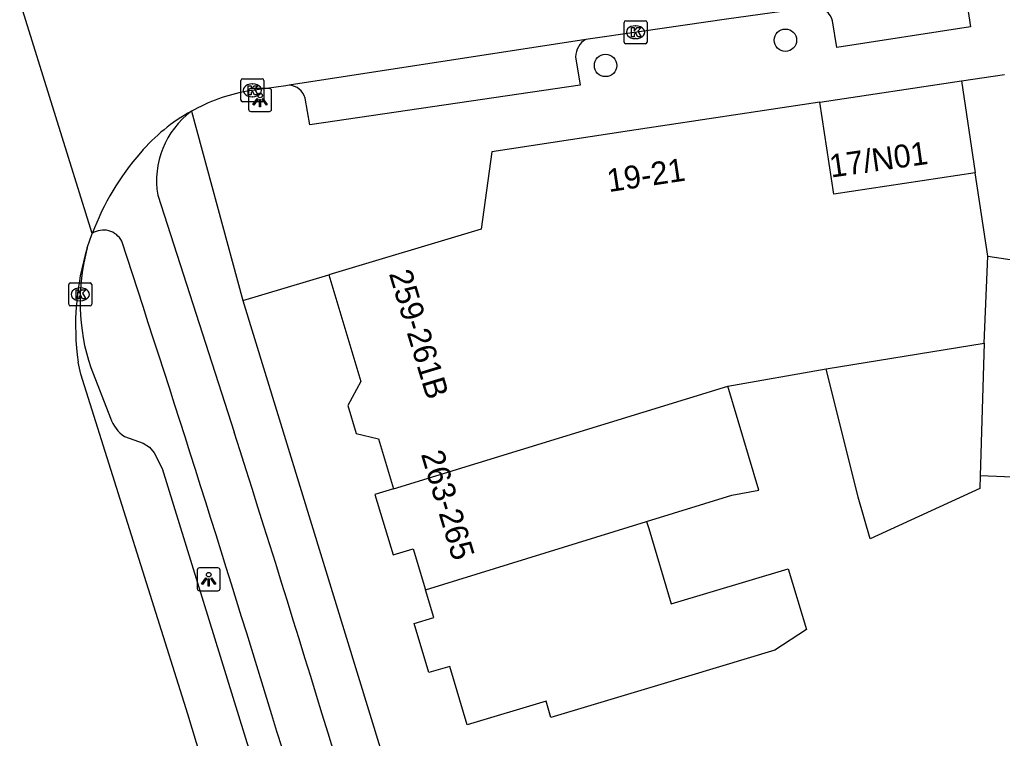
# Model space of a CAD drawing. Extents: x 162347 to 162868, y 381221 to 381813.
# Drawn here: x 162506 to 162548.83, y 381328.51 to 381359.83 of the extents above; entities that cross this region are included whole.
import ezdxf

# ---------------------------------------------------------------- set-up
doc = ezdxf.new("R2010")
doc.units = 0
for name, color, linetype in [('IMGEO_Boom', 7, 'Continuous'), ('IMGEO_Fietspad_open', 7, 'Continuous'), ('IMGEO_Kolk', 7, 'Continuous'), ('IMGEO_Lichtpunt', 7, 'Continuous'), ('IMGEO_Pand', 7, 'Continuous'), ('IMGEO_Pand_nummerreeks', 7, 'Continuous'), ('IMGEO_Parkeervlak_open', 7, 'Continuous'), ('IMGEO_Rijbaan_lokaal_gesloten', 7, 'Continuous'), ('IMGEO_Rijbaan_regionaal_gesloten', 7, 'Continuous'), ('IMGEO_Voetpad_open', 7, 'Continuous')]:
    doc.layers.add(name, color=color, linetype=linetype)

msp = doc.modelspace()

# ---------------------------------------------------------------- linework, layer by layer
at = {"layer": 'IMGEO_Boom'}
for centre in [(162539.372, 381358.93), (162531.535, 381357.832)]:
    msp.add_circle(centre, 0.489, dxfattribs=at)
at = {"layer": 'IMGEO_Fietspad_open'}
msp.add_lwpolyline([(162512.017, 381352.181), (162515.348, 381341.849)], dxfattribs=at)
for centre, radius, start, end in [((162515.746, 381352.807), 3.781, 126.7231, 189.5336), ((162509.653, 381349.759), 0.898, 27.2906, 122.9242), ((161424.172, 380994.375), 1143.063, 16.937549, 18.135487), ((161515.414, 381022.471), 1049.7, 16.214141, 17.713421)]:
    msp.add_arc(centre, radius, start, end, dxfattribs=at)
at = {"layer": 'IMGEO_Kolk'}
for p, q in [((162532.344, 381358.853), (162532.344, 381359.705)), ((162532.419, 381359.779), (162533.271, 381359.779)), ((162533.345, 381359.705), (162533.345, 381358.853)), ((162532.832, 381359.559), (162532.857, 381359.559)), ((162533.271, 381358.779), (162532.419, 381358.779)), ((162532.855, 381358.999), (162532.83, 381358.999)), ((162515.643, 381356.323), (162515.643, 381357.175)), ((162515.718, 381357.249), (162516.57, 381357.249)), ((162516.644, 381357.175), (162516.644, 381356.323)), ((162516.131, 381357.029), (162516.156, 381357.029)), ((162516.57, 381356.249), (162515.718, 381356.249)), ((162516.154, 381356.469), (162516.129, 381356.469)), ((162508.143, 381347.429), (162508.143, 381348.281)), ((162508.218, 381348.355), (162509.07, 381348.355)), ((162508.631, 381348.135), (162508.656, 381348.135)), ((162509.144, 381348.281), (162509.144, 381347.429)), ((162509.07, 381347.355), (162508.218, 381347.355)), ((162508.654, 381347.575), (162508.629, 381347.575))]:
    msp.add_line(p, q, dxfattribs=at)
for points in [[(162532.344, 381358.853), (162532.344, 381359.705)], [(162532.419, 381359.779), (162533.271, 381359.779)], [(162533.345, 381359.705), (162533.345, 381358.853)], [(162532.665, 381359.479), (162532.788, 381359.479), (162532.788, 381359.328), (162532.918, 381359.479), (162533.082, 381359.479), (162532.936, 381359.328), (162533.089, 381359.079), (162532.937, 381359.079), (162532.852, 381359.243), (162532.788, 381359.176), (162532.788, 381359.079), (162532.665, 381359.079), (162532.665, 381359.479)], [(162533.271, 381358.779), (162532.419, 381358.779)], [(162515.643, 381356.323), (162515.643, 381357.175)], [(162515.718, 381357.249), (162516.57, 381357.249)], [(162516.644, 381357.175), (162516.644, 381356.323)], [(162515.964, 381356.949), (162516.087, 381356.949), (162516.087, 381356.798), (162516.217, 381356.949), (162516.381, 381356.949), (162516.235, 381356.798), (162516.388, 381356.549), (162516.236, 381356.549), (162516.151, 381356.713), (162516.087, 381356.646), (162516.087, 381356.549), (162515.964, 381356.549), (162515.964, 381356.949)], [(162516.57, 381356.249), (162515.718, 381356.249)], [(162508.143, 381347.429), (162508.143, 381348.281)], [(162508.218, 381348.355), (162509.07, 381348.355)], [(162509.144, 381348.281), (162509.144, 381347.429)], [(162508.464, 381348.055), (162508.587, 381348.055), (162508.587, 381347.904), (162508.717, 381348.055), (162508.881, 381348.055), (162508.735, 381347.904), (162508.888, 381347.655), (162508.736, 381347.655), (162508.651, 381347.819), (162508.587, 381347.752), (162508.587, 381347.655), (162508.464, 381347.655), (162508.464, 381348.055)], [(162509.07, 381347.355), (162508.218, 381347.355)]]:
    msp.add_lwpolyline(points, dxfattribs=at)
for centre, start, end in [((162532.421, 381359.703), 91.552, 178.448), ((162532.421, 381359.703), 91.552, 178.448), ((162533.269, 381359.703), 1.552, 88.448), ((162533.269, 381359.703), 1.552, 88.448), ((162532.421, 381358.855), 181.552, 268.448), ((162532.421, 381358.855), 181.552, 268.448), ((162533.269, 381358.855), 271.552, 358.448), ((162533.269, 381358.855), 271.552, 358.448), ((162515.72, 381357.173), 91.552, 178.448), ((162515.72, 381357.173), 91.552, 178.448), ((162516.568, 381357.173), 1.552, 88.448), ((162516.568, 381357.173), 1.552, 88.448), ((162515.72, 381356.325), 181.552, 268.448), ((162515.72, 381356.325), 181.552, 268.448), ((162516.568, 381356.325), 271.552, 358.448), ((162516.568, 381356.325), 271.552, 358.448), ((162508.22, 381348.279), 91.552, 178.448), ((162508.22, 381348.279), 91.552, 178.448), ((162509.068, 381348.279), 1.552, 88.448), ((162509.068, 381348.279), 1.552, 88.448), ((162508.22, 381347.431), 181.552, 268.448), ((162508.22, 381347.431), 181.552, 268.448), ((162509.068, 381347.431), 271.552, 358.448), ((162509.068, 381347.431), 271.552, 358.448)]:
    msp.add_arc(centre, 0.0765, start, end, dxfattribs=at)
for centre, major_axis, ratio, start_param, end_param in [((162532.831, 381359.279), (-0.387, 0.002), 0.722429, 4.712389, 7.853982), ((162532.856, 381359.279), (-0.39, 0.002), 0.717154, 1.570796, 4.712389), ((162516.13, 381356.749), (-0.387, 0.002), 0.722429, 4.712389, 7.853982), ((162516.155, 381356.749), (-0.39, 0.002), 0.717154, 1.570796, 4.712389), ((162508.63, 381347.855), (-0.387, 0.002), 0.722429, 4.712389, 7.853982), ((162508.655, 381347.855), (-0.39, 0.002), 0.717154, 1.570796, 4.712389)]:
    msp.add_ellipse(centre, major_axis=major_axis, ratio=ratio, start_param=start_param, end_param=end_param, dxfattribs=at)
at = {"layer": 'IMGEO_Lichtpunt'}
for p, q in [((162515.981, 381356.729), (162515.981, 381355.922)), ((162515.981, 381356.729), (162515.981, 381355.922)), ((162516.883, 381356.824), (162516.075, 381356.824)), ((162516.883, 381356.824), (162516.075, 381356.824)), ((162516.977, 381355.922), (162516.977, 381356.729)), ((162516.977, 381355.922), (162516.977, 381356.729)), ((162516.075, 381355.828), (162516.883, 381355.828)), ((162516.075, 381355.828), (162516.883, 381355.828)), ((162513.742, 381335.841), (162513.742, 381335.034)), ((162513.742, 381335.841), (162513.742, 381335.034)), ((162514.644, 381335.936), (162513.836, 381335.936)), ((162514.644, 381335.936), (162513.836, 381335.936)), ((162514.738, 381335.034), (162514.738, 381335.841)), ((162514.738, 381335.034), (162514.738, 381335.841)), ((162513.836, 381334.94), (162514.644, 381334.94)), ((162513.836, 381334.94), (162514.644, 381334.94))]:
    msp.add_line(p, q, dxfattribs=at)
for points in [[(162516.355, 381356.393), (162516.394, 381356.365), (162516.206, 381356.103), (162516.168, 381356.13), (162516.355, 381356.393)], [(162516.457, 381356.345), (162516.504, 381356.345), (162516.504, 381356.023), (162516.457, 381356.023), (162516.457, 381356.345)], [(162516.567, 381356.365), (162516.605, 381356.392), (162516.792, 381356.13), (162516.753, 381356.102), (162516.567, 381356.365)], [(162514.116, 381335.505), (162514.155, 381335.477), (162513.967, 381335.215), (162513.929, 381335.242), (162514.116, 381335.505)], [(162514.218, 381335.457), (162514.265, 381335.457), (162514.265, 381335.135), (162514.218, 381335.135), (162514.218, 381335.457)], [(162514.328, 381335.477), (162514.366, 381335.504), (162514.553, 381335.242), (162514.514, 381335.214), (162514.328, 381335.477)]]:
    msp.add_lwpolyline(points, dxfattribs=at)
for centre in [(162516.48, 381356.527), (162514.241, 381335.639)]:
    msp.add_circle(centre, 0.0994, dxfattribs=at)
for centre, start, end in [((162516.075, 381356.729), 90, 180), ((162516.075, 381356.729), 90, 180), ((162516.883, 381356.729), 0, 90), ((162516.883, 381356.729), 0, 90), ((162516.075, 381355.922), 180, 270), ((162516.075, 381355.922), 180, 270), ((162516.883, 381355.922), 270, 0), ((162516.883, 381355.922), 270, 360), ((162513.836, 381335.841), 90, 180), ((162513.836, 381335.841), 90, 180), ((162514.644, 381335.841), 0, 90), ((162514.644, 381335.841), 0, 90), ((162513.836, 381335.034), 180, 270), ((162513.836, 381335.034), 180, 270), ((162514.644, 381335.034), 270, 0), ((162514.644, 381335.034), 270, 360)]:
    msp.add_arc(centre, 0.0946, start, end, dxfattribs=at)
at = {"layer": 'IMGEO_Pand'}
for points in [[(162540.878, 381356.227), (162547.044, 381357.157)], [(162547.044, 381357.157), (162547.648, 381353.152)], [(162540.878, 381356.227), (162532.585, 381354.976), (162526.582, 381354.07), (162526.112, 381350.704), (162519.471, 381348.712)], [(162547.648, 381353.152), (162541.482, 381352.222), (162540.878, 381356.227)], [(162548.193, 381349.527), (162547.648, 381353.152)], [(162548.193, 381349.527), (162550.914, 381349.118), (162560.676, 381347.652), (162560.347, 381339.448), (162551.036, 381339.821), (162547.859, 381339.948)], [(162548.037, 381345.733), (162548.193, 381349.527)], [(162519.471, 381348.712), (162520.864, 381344.065), (162520.296, 381343.01), (162520.66, 381341.796), (162521.639, 381341.564), (162522.296, 381339.376)], [(162541.145, 381344.608), (162548.037, 381345.733)], [(162548.037, 381345.733), (162547.859, 381339.948)], [(162536.857, 381343.859), (162541.145, 381344.608)], [(162547.859, 381339.948), (162547.841, 381339.39), (162543.063, 381337.202), (162542.54, 381339.013), (162541.145, 381344.608)], [(162522.296, 381339.376), (162536.857, 381343.859)], [(162533.322, 381337.952), (162537.044, 381339.099), (162538.218, 381339.323), (162536.857, 381343.859)], [(162522.296, 381339.376), (162521.487, 381339.134), (162522.276, 381336.504), (162523.155, 381336.768), (162523.69, 381334.985)], [(162533.322, 381337.952), (162533.414, 381337.645), (162534.399, 381334.362), (162539.5, 381335.892), (162540.291, 381333.255), (162538.907, 381332.343), (162533.941, 381330.854), (162529.151, 381329.417), (162528.94, 381330.122), (162525.508, 381329.093), (162524.744, 381331.642), (162523.837, 381331.37), (162523.195, 381333.509), (162524.055, 381333.767), (162523.69, 381334.985)], [(162523.69, 381334.985), (162533.322, 381337.952)]]:
    msp.add_lwpolyline(points, dxfattribs=at)
at = {"layer": 'IMGEO_Parkeervlak_open'}
for points in [[(162509.097, 381344.675), (162509.963, 381342.467)], [(162510.574, 381341.66), (162511.386, 381341.368), (162511.659, 381341.199), (162511.867, 381340.946), (162512.219, 381340.273), (162517.818, 381322.123), (162520.103, 381314.39), (162520.562, 381312.814), (162522.874, 381305.299), (162525.989, 381295.243), (162527.307, 381291.065)]]:
    msp.add_lwpolyline(points, dxfattribs=at)
for centre, radius, start, end in [((162517.554, 381347.52), 8.922, 164.6666, 198.5914), ((162511.426, 381342.94), 1.537, 197.9086, 236.3519)]:
    msp.add_arc(centre, radius, start, end, dxfattribs=at)
at = {"layer": 'IMGEO_Rijbaan_lokaal_gesloten'}
for points in [[(162540.681, 381360.393), (162536.811, 381359.842), (162533.107, 381359.314), (162530.674, 381358.967)], [(162530.674, 381358.967), (162517.749, 381356.974)], [(162517.749, 381356.974), (162517.595, 381356.95), (162515.923, 381356.718)]]:
    msp.add_lwpolyline(points, dxfattribs=at)
for centre, radius, start, end in [((162517.426, 381348.736), 8.122, 100.6656, 119.0287), ((162517.403, 381348.77), 8.081, 119.0026, 139.393), ((162519.9, 381346.481), 11.467, 138.8297, 159.4154)]:
    msp.add_arc(centre, radius, start, end, dxfattribs=at)
at = {"layer": 'IMGEO_Rijbaan_regionaal_gesloten'}
for points in [[(162509.165, 381350.513), (162506.001, 381360.676)], [(162508.949, 381349.879), (162509.165, 381350.513)], [(162526.558, 381283.713), (162525.308, 381288.359), (162522.207, 381299.376), (162517.911, 381314.419), (162513.331, 381329.554), (162508.674, 381344.38), (162508.55, 381344.901)]]:
    msp.add_lwpolyline(points, dxfattribs=at)
msp.add_arc((162519.855, 381346.5), 11.418, 162.7853, 188.0495, dxfattribs=at)
at = {"layer": 'IMGEO_Voetpad_open'}
for points in [[(162547.272, 381360.656), (162547.445, 381359.515), (162541.612, 381358.609), (162541.426, 381359.776)], [(162530.228, 381358.208), (162530.427, 381356.978), (162518.647, 381355.242), (162518.448, 381356.408)], [(162547.044, 381357.157), (162548.922, 381357.44)], [(162513.485, 381355.838), (162515.721, 381347.587)], [(162515.721, 381347.587), (162519.471, 381348.712)], [(162515.721, 381347.587), (162528.199, 381306.949), (162530.18, 381307.505), (162531.812, 381307.964), (162533.129, 381308.331)]]:
    msp.add_lwpolyline(points, dxfattribs=at)
for centre, radius, start, end in [((162540.623, 381359.565), 0.83, 14.723, 86.0147), ((162531.122, 381358.193), 0.894, 120.0688, 179.0529), ((162517.694, 381356.192), 0.784, 15.9979, 86.0059)]:
    msp.add_arc(centre, radius, start, end, dxfattribs=at)

# ---------------------------------------------------------------- texts
at = {"layer": 'IMGEO_Pand_nummerreeks'}
for s, rotation, p in [('17/N01', 7.9893, (162541.363, 381352.944)), ('19-21', 8.5829, (162531.676, 381352.31)), ('259-261B', 286.8333, (162522.088, 381348.762)), ('263-265', 286.7015, (162523.483, 381340.894))]:
    msp.add_text(s, height=1, rotation=rotation, dxfattribs=at).set_placement(p)

doc.saveas('drawing.dxf')
